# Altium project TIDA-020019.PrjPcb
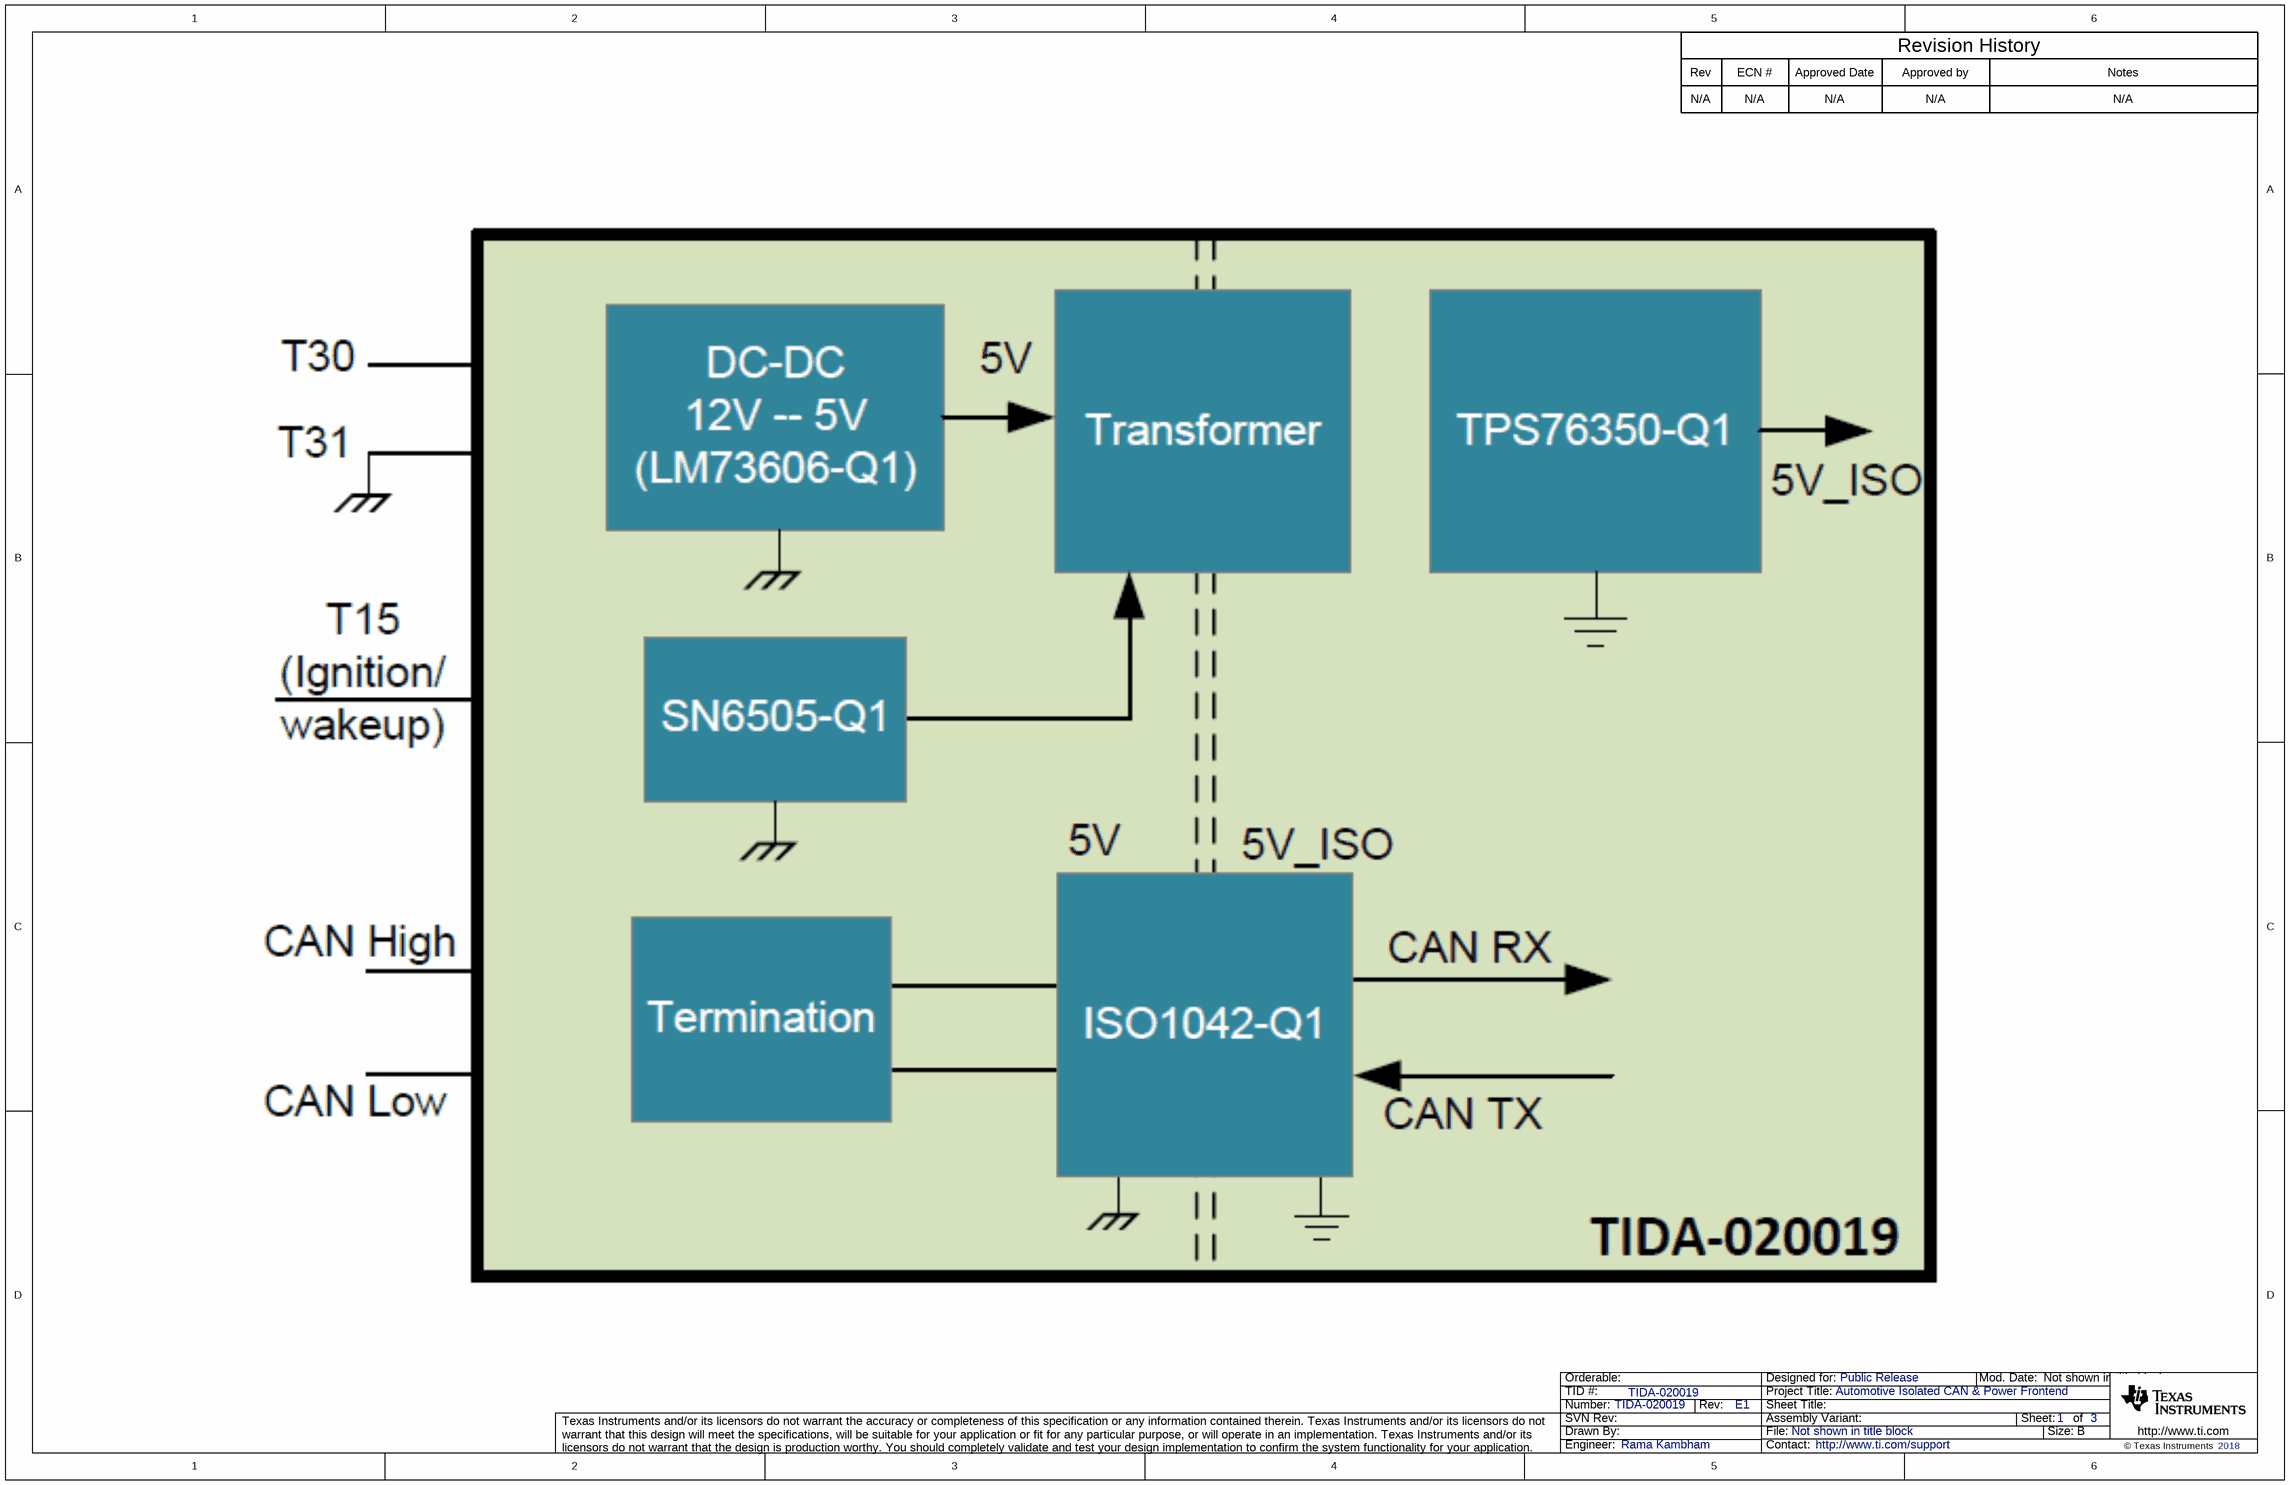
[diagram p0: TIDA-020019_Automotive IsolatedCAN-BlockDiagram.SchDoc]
CopyrightYear: 2018; PCB_Layout: Rama Kambham; PCB_Rev: E1; PRJ_Customer: Public Release; PRJ_Engineer: Rama Kambham; PRJ_Number: TIDA-020019; PRJ_Title: Automotive Isolated CAN & Power Frontend; SCH_Rev: E1; TechSupport: http://www.ti.com/support; TID: TIDA-020019
3 sheets, 62 parts. Net scope: global (net labels, ports and power ports of the same name join across sheets).
Board file: TIDA-020019_AutomotiveIsolatedCAN-Layout.PcbDoc
Sheets:
  TIDA-020019_Automotive IsolatedCAN-BlockDiagram.SchDoc
  TIDA-020019_Automotive IsolatedCAN-SCH-Page1.SchDoc
  TIDA-020019_Automotive IsolatedCAN-SCH-HW.SchDoc

## Sheet TIDA-020019_Automotive IsolatedCAN-BlockDiagram.SchDoc
size 431 x 279 mm; Date: Not shown in title block; ApprovedBy: Not shown in title block; CheckedBy: Not shown in title block; Author: Not shown in title block; CompanyName: Not shown in title block; Engineer: Not shown in title block; Organization: Not shown in title block; Address1: Not shown in title block; Address2: Not shown in title block; Address3: Not shown in title block; Address4: Not shown in title block; DocumentNumber: 1; Revision: Use project parameter SCH_Rev; SheetNumber: 1; SheetTotal: 3; PageSetup: Record=PageOptions¦CenterHorizontal=True¦CenterVertical=True¦PrintScale=1.00¦XCorrection=1.00¦YCorrection=1.00¦PrintKind=0¦BorderSize=5000000¦LeftOffset=0¦BottomOffset=0¦Orientation=2¦PaperLength=1000¦PaperWidth=1000¦Scale=100¦PaperSource=15¦PrintQuality=600¦MediaType=1¦DitherType=10¦PaperKind=Letter¦PrintScaleMode=1

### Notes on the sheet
- Rev
- N/A
- ECN #
- Approved Date
- Approved by
- Revision History
- Notes

## Sheet TIDA-020019_Automotive IsolatedCAN-SCH-Page1.SchDoc
size 431 x 279 mm; Date: Not shown in title block; ApprovedBy: Not shown in title block; CheckedBy: Not shown in title block; Author: Not shown in title block; CompanyName: Not shown in title block; DrawnBy: Rama Kambham; Engineer: Not shown in title block; Organization: Not shown in title block; Address1: Not shown in title block; Address2: Not shown in title block; Address3: Not shown in title block; Address4: Not shown in title block; DocumentNumber: 2; Revision: Use project parameter SCH_Rev; SheetNumber: 2; SheetTotal: 3; PageSetup: Record=PageOptions¦CenterHorizontal=True¦CenterVertical=True¦PrintScale=1.00¦XCorrection=1.00¦YCorrection=1.00¦PrintKind=0¦BorderSize=5000000¦LeftOffset=0¦BottomOffset=0¦Orientation=2¦PaperLength=1000¦PaperWidth=1000¦Scale=100¦PaperSource=15¦PrintQuality=600¦MediaType=1¦DitherType=10¦PaperKind=Letter¦PrintScaleMode=1
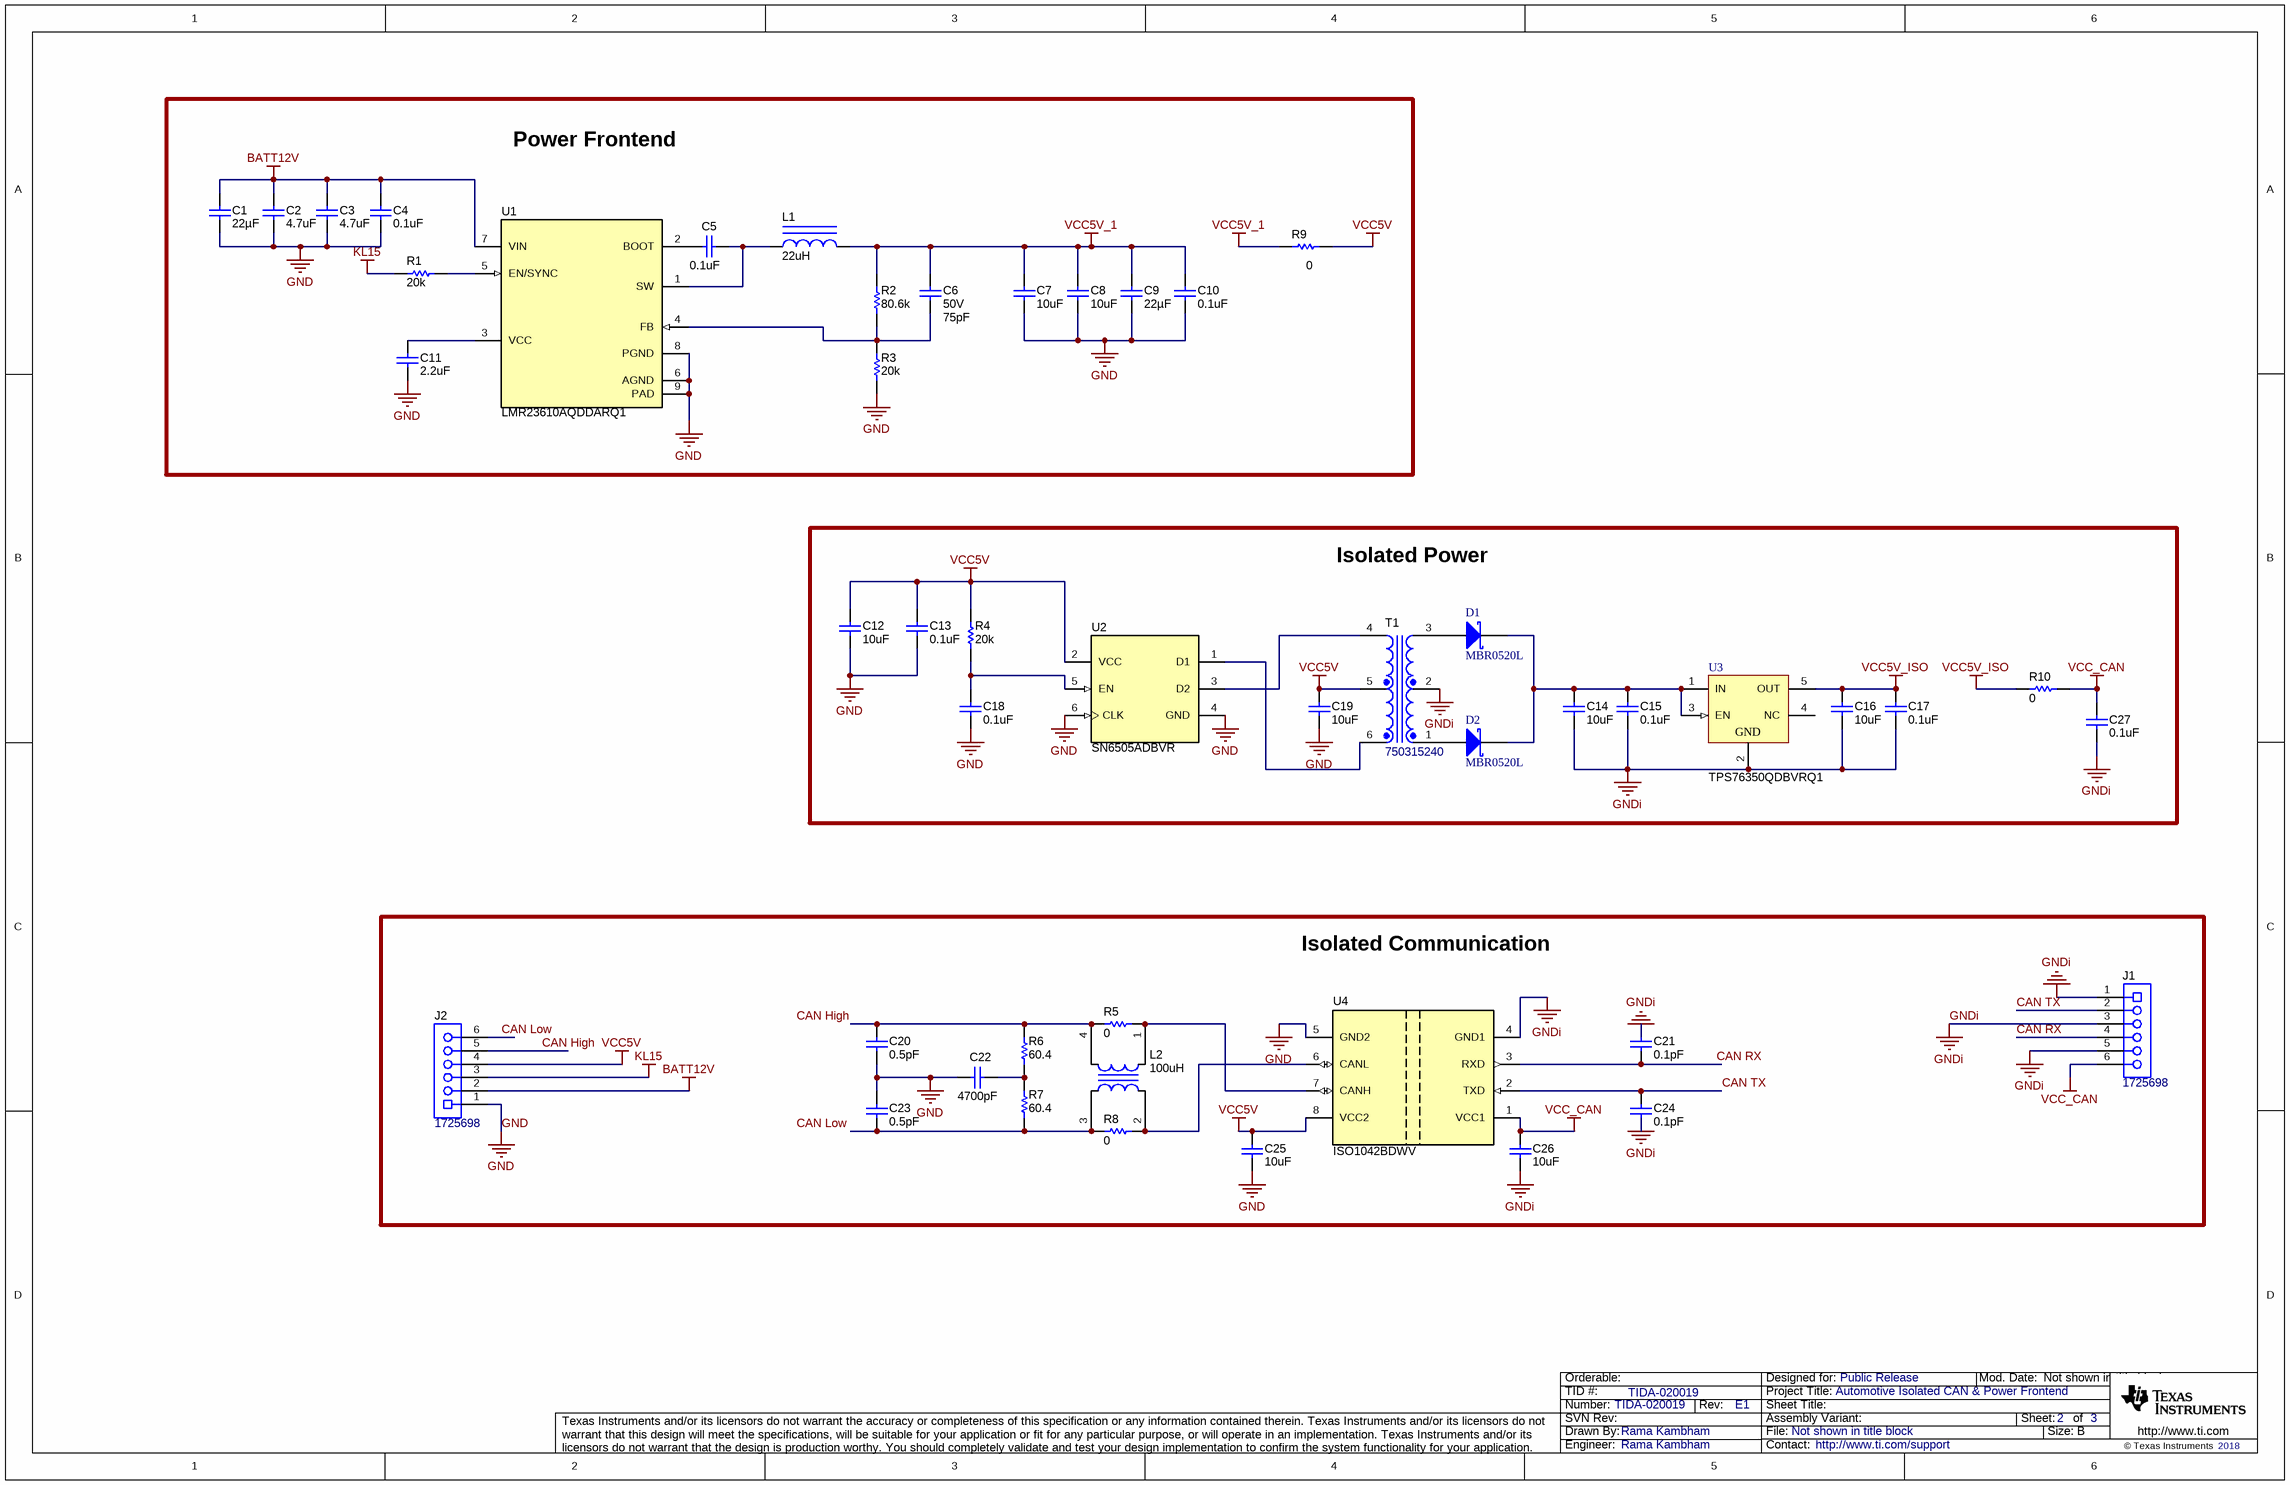
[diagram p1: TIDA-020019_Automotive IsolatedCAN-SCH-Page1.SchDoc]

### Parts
C1  ValueDisplayed: 22µF  [0805L]  (hidden comment: GRT21BR61E226ME13L)
C2  ValueDisplayed: 4.7uF  [0805L]  (hidden comment: GRT21BR61H475KE13L)
C3  ValueDisplayed: 4.7uF  [0805L]  (hidden comment: GRT21BR61H475KE13L)
C4  ValueDisplayed: 0.1uF  [0603S]  (hidden comment: CGA3E2X7R1H104K080AA)
C5  ValueDisplayed: 0.1uF  [0603S]  (hidden comment: GCM188R71C104KA37J)
C6  VDC_V: 50V  ValueDisplayed: 75pF  [0402S]  (hidden comment: GRM1555C1H750JA01D)
C7  ValueDisplayed: 10uF  [0603S]  (hidden comment: GRT188C81A106ME13D)
C8  ValueDisplayed: 10uF  [0603S]  (hidden comment: GRT188C81A106ME13D)
C9  ValueDisplayed: 22µF  [0805L]  (hidden comment: GRT21BR61E226ME13L)
C10  ValueDisplayed: 0.1uF  [0402S]  (hidden comment: GCM155R71A104KA55D)
C11  ValueDisplayed: 2.2uF  [0603S]  (hidden comment: GRT188R61H225KE13D)
C12  ValueDisplayed: 10uF  [0603S]  (hidden comment: GRT188C81A106ME13D)
C13  ValueDisplayed: 0.1uF  [0402S]  (hidden comment: GCM155R71A104KA55D)
C14  ValueDisplayed: 10uF  [0603S]  (hidden comment: GRT188C81A106ME13D)
C15  ValueDisplayed: 0.1uF  [0402S]  (hidden comment: GCM155R71A104KA55D)
C16  ValueDisplayed: 10uF  [0603S]  (hidden comment: GRT188C81A106ME13D)
C17  ValueDisplayed: 0.1uF  [0402S]  (hidden comment: GCM155R71A104KA55D)
C18  ValueDisplayed: 0.1uF  [0402S]  (hidden comment: GCM155R71A104KA55D)
C19  ValueDisplayed: 10uF  [0603S]  (hidden comment: GRT188C81A106ME13D)
C20  ValueDisplayed: 0.5pF  [0805L]  (hidden comment: GQM2195C2AR50CB01D)
C21  ValueDisplayed: 0.1pF  [0402S]  (hidden comment: GRM1555C1HR10WA01D)
C22  ValueDisplayed: 4700pF  [0603S]  (hidden comment: CGA3E2X7R2A472K080AA)
C23  ValueDisplayed: 0.5pF  [0805L]  (hidden comment: GQM2195C2AR50CB01D)
C24  ValueDisplayed: 0.1pF  [0402S]  (hidden comment: GRM1555C1HR10WA01D)
C25  ValueDisplayed: 10uF  [0603S]  (hidden comment: GRT188C81A106ME13D)
C26  ValueDisplayed: 10uF  [0603S]  (hidden comment: GRT188C81A106ME13D)
C27  ValueDisplayed: 0.1uF  [0402S]  (hidden comment: GCM155R71A104KA55D)
D1  MBR0520L  [ONSC-SOD-123-2-425-04_V]
D2  MBR0520L  [ONSC-SOD-123-2-425-04_V]
J1  1725698  [Phoenix_1725698]
J2  1725698  [Phoenix_1725698]
L1  ValueDisplayed: 22uH  [WE-PD_7345_PlasticBase]  (hidden comment: 7447779122)
L2  ValueDisplayed: 100uH  [ACT45B_NoSilk]  (hidden comment: ACT45B-101-2P-TL003)
R1  ValueDisplayed: 20k  [0402S]  (hidden comment: ERJ-2GEJ203X)
R2  ValueDisplayed: 80.6k  [0402S]  (hidden comment: CRCW040280K6FKED)
R3  ValueDisplayed: 20k  [0402S]  (hidden comment: ERJ-2GEJ203X)
R4  ValueDisplayed: 20k  [0402S]  (hidden comment: ERJ-2GEJ203X)
R5  ValueDisplayed: 0  [0402S]  (hidden comment: CRCW04020000Z0ED)
R6  ValueDisplayed: 60.4  [1206L]  (hidden comment: ERJ-8ENF60R4V)
R7  ValueDisplayed: 60.4  [1206L]  (hidden comment: ERJ-8ENF60R4V)
R8  ValueDisplayed: 0  [0402S]  (hidden comment: CRCW04020000Z0ED)
R9  ValueDisplayed: 0  [0402S]  (hidden comment: CRCW04020000Z0ED)
R10  ValueDisplayed: 0  [0402S]  (hidden comment: CRCW04020000Z0ED)
T1  750315240  [Wurth_750315240]
U1  LMR23610AQDDARQ1  [DDA0008E_L]
U2  SN6505ADBVR  [DBV0006A_L]
U3  TPS76350QDBVRQ1  [DBV0005A_N]
U4  ISO1042BDWV  [DWV0008A]

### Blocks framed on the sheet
Power Frontend: C1-C11 L1 R1-R3 R9 U1
Isolated Power: C12-C19 C27 D1 D2 R4 R10 T1 U2 U3
Isolated Communication: C20-C26 J1 J2 L2 R5-R8 U4

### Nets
BATT12V: C1.1 C2.1 C3.1 C4.1 J2.2 U1.7(VIN)
GND: C1.2 C2.2 C3.2 C4.2 C7.2 C8.2 C9.2 C10.2 C11.2 C12.2 C13.2 C18.2 C19.2 C20.2 C22.2 C23.1 C25.2 J2.1 R3.1 U1.6(AGND) U1.8(PGND) U1.9(PAD) U2.4(GND) U2.6(CLK) U4.5(GND2)
GNDi: C14.2 C15.2 C16.2 C17.2 C21.1 C24.2 C26.2 C27.2 J1.1 J1.3 J1.5 T1.2 U3.2(GND) U4.4(GND1)
KL15: J2.3 R1.2
VCC5V: C12.1 C13.1 C19.1 C25.1 J2.4 R4.2 R9.2 T1.5 U2.2(VCC) U4.8(VCC2)
VCC5V_1: C6.1 C7.1 C8.1 C9.1 C10.1 L1.2 R2.2 R9.1
VCC5V_ISO: C16.1 C17.1 R10.1 U3.5(OUT)
VCC_CAN: C26.1 C27.1 J1.6 R10.2 U4.1(VCC1)
CAN High: J2.5
CAN Low: J2.6
CAN RX: C21.2 J1.4 U4.3(RXD)
CAN TX: C24.1 J1.2 U4.2(TXD)
NetC5_1: C5.1 L1.1 U1.1(SW)
NetC5_2: C5.2 U1.2(BOOT)
NetC6_2: C6.2 R2.1 R3.2 U1.4(FB)
NetC11_1: C11.1 U1.3(VCC)
NetC14_1: C14.1 C15.1 D1.1(K) D2.1(K) U3.1(IN) U3.3(EN)
NetC18_1: C18.1 R4.1 U2.5(EN)
NetC20_1: C20.1 L2.4 R5.1 R6.2
NetC22_1: C22.1 R6.1 R7.2
NetC23_2: C23.2 L2.3 R7.1 R8.1
NetD1_2: D1.2(A) T1.3
NetD2_2: D2.2(A) T1.1
NetL2_1: L2.1 R5.2 U4.7(CANH)
NetL2_2: L2.2 R8.2 U4.6(CANL)
NetR1_1: R1.1 U1.5(EN/SYNC)
NetT1_4: T1.4 U2.3(D2)
NetT1_6: T1.6 U2.1(D1)

Not connected (* = marked no-connect by the designer): U3 4(NC)

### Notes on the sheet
- Labels drawn without touching a wire or pin: CAN High, CAN Low

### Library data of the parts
C1 C9 = CMP-0084680-1: CAP, CERM, 22 µF, 25 V,+/- 20%, X5R, AEC-Q200 Grade 3, 0805; Manufacturer: MuRata; SizeX_mm: 2; SizeAreaWB_mm2: 6.75; Cap_Case: 0805; AEC Grade: 3; SizeY_mm: 1.25; SizeArea_mm2: 2.5; SizeZ_mm: 1.45; U/M: EA; Polarized: N; VDC_V: 25V; AEC Category: Q200; Value: 22uF; TaMin_C: -55°C; AEC Qualified: Y; TaMax_C: 85°C
C2 C3 = CMP-0008380-1: CAP, CERM, 4.7 uF, 50 V, +/- 10%, X5R, AEC-Q200 Grade 3, 0805; Manufacturer: MuRata; TaMin_C: -55°C; Polarized: N; SizeAreaWB_mm2: 6.75; Value1: Unknown; U/M: EA; Value: 4.7uF; TaMax_C: 85°C; SizeZ_mm: 1.45; SizeX_mm: 2; SizeY_mm: 1.25; Cap_Case: 0805; Value2: 50V; SizeArea_mm2: 2.5; AEC Qualified: Y; Cap_F: 4.7µF; AEC Grade: 3; AEC Category: Q200
C4 = CMP-0007078-1: CAP, CERM, 0.1 uF, 50 V, +/- 10%, X7R, AEC-Q200 Grade 1, 0603; Manufacturer: TDK; TaMin_C: -55°C; ESR_ohm: 0.0296; Polarized: N; SizeAreaWB_mm2: 4.68; Value1: 0.0296 ohm; U/M: EA; Value: 0.1uF; TaMax_C: 125°C; SizeZ_mm: 1; SizeX_mm: 1.6; SizeY_mm: 0.8; Cap_Case: 0603; Value2: 50V; SizeArea_mm2: 1.28; AEC Qualified: Y; Cap_F: 100nF; IRMS_A: 971.99mA; AEC Category: Q200
C5 = CMP-0007135-4: CAP, CERM, 0.1 uF, 16 V, +/- 10%, X7R, AEC-Q200 Grade 1, 0603; Manufacturer: MuRata; TaMin_C: -55°C; Polarized: N; SizeAreaWB_mm2: 4.68; Value1: Unknown; U/M: EA; Value: 0.1uF; TaMax_C: 125°C; SizeZ_mm: 1; SizeX_mm: 1.6; SizeY_mm: 0.8; Cap_Case: 0603; Value2: 16V; SizeArea_mm2: 1.28; AEC Qualified: Y; Cap_F: 100nF; AEC Category: Q200
C6 = CMP-0006489-1: CAP, CERM, 75 pF, 50 V, +/- 5%, C0G/NP0, 0402; Manufacturer: MuRata; TaMin_C: -55°C; Polarized: N; SizeAreaWB_mm2: 3; Value1: Unknown; U/M: EA; Value: 75pF; TaMax_C: 125°C; SizeZ_mm: 0.6; SizeX_mm: 1; SizeY_mm: 0.5; Cap_Case: 0402; AEC Category: Q200
C7 C8 C12 C14 C16 C19 C25 C26 = CMP-0007500-1: CAP, CERM, 10 uF, 10 V, +/- 20%, X6S, AEC-Q200 Grade 2, 0603; Manufacturer: MuRata; TaMin_C: -55°C; Polarized: N; SizeAreaWB_mm2: 4.68; Value1: Unknown; U/M: EA; Value: 10uF; TaMax_C: 105°C; SizeZ_mm: 1; SizeX_mm: 1.6; SizeY_mm: 0.8; Cap_Case: 0603; Value2: 10V; SizeArea_mm2: 1.28; AEC Qualified: Y; Cap_F: 10µF; AEC Grade: 2; AEC Category: Q200
C10 C13 C15 C17 C18 C27 = CMP-0006350-1: CAP, CERM, 0.1 uF, 10 V, +/- 10%, X7R, AEC-Q200 Grade 1, 0402; Manufacturer: MuRata; TaMin_C: -55°C; Polarized: N; SizeAreaWB_mm2: 3; Value1: Unknown; U/M: EA; Value: 0.1uF; TaMax_C: 125°C; SizeZ_mm: 0.6; SizeX_mm: 1; SizeY_mm: 0.5; Cap_Case: 0402; Value2: 10V; AEC Qualified: Y; Cap_F: 100nF; AEC Category: Q200
C11 = CMP-0007502-1: CAP, CERM, 2.2 uF, 50 V, +/- 10%, X5R, AEC-Q200 Grade 3, 0603; Manufacturer: MuRata; TaMin_C: -55°C; Polarized: N; SizeAreaWB_mm2: 4.68; Value1: Unknown; U/M: EA; Value: 2.2uF; TaMax_C: 85°C; SizeZ_mm: 1; SizeX_mm: 1.6; SizeY_mm: 0.8; Cap_Case: 0603; Value2: 50V; SizeArea_mm2: 1.28; AEC Qualified: Y; Cap_F: 2.2µF; AEC Grade: 3; AEC Category: Q200
C20 C23 = CMP-0008057-1: CAP, CERM, 0.5 pF, 100 V, +/- 5%, C0G/NP0, 0805; Manufacturer: MuRata; TaMin_C: -55°C; Polarized: N; SizeAreaWB_mm2: 6.75; Value1: Unknown; U/M: EA; Value: 0.5pF; TaMax_C: 125°C; SizeZ_mm: 1.45; SizeX_mm: 2; SizeY_mm: 1.25; Cap_Case: 0805; Value2: 100V; SizeArea_mm2: 2.5; AEC Category: Q200
C21 C24 = CMP-0006499-2: CAP, CERM, 0.1pF, 50 V, +/- 50%, C0G/NP0, 0402; Manufacturer: MuRata; TaMin_C: -55°C; Polarized: N; SizeAreaWB_mm2: 3; Value1: Unknown; U/M: EA; TaMax_C: 125°C; SizeZ_mm: 0.6; SizeX_mm: 1; SizeY_mm: 0.5; Cap_Case: 0402; Value2: 50V; AEC Category: Q200
C22 = CMP-0007088-4: CAP, CERM, 4700 pF, 100 V, +/- 10%, X7R, AEC-Q200 Grade 1, 0603; Manufacturer: TDK; TaMin_C: -55°C; ESR_ohm: 0.469862; Polarized: N; SizeAreaWB_mm2: 4.68; Value1: 0.469862 ohm; U/M: EA; Value: 4700pF; TaMax_C: 125°C; SizeZ_mm: 1; SizeX_mm: 1.6; SizeY_mm: 0.8; Cap_Case: 0603; Value2: 100V; SizeArea_mm2: 1.28; AEC Qualified: Y; Cap_F: 4.7nF; IRMS_A: 323.35mA; AEC Category: Q200
D1 D2 = CMP-2000-04926-1: Schottky Diode, 20V, 0.2A, 2-pin SOD-123, RoHS, Tape and Reel; Manufacturer: FairchildSemiconductor; Peak Forward Voltage: 0.385V; Rad Hard: No; Peak Non-Repetitive Surge Current: 5.5A; Peak Average Forward Current: 0.5A; Peak Reverse Current: 250uA; Configuration: Single
J1 J2 = CMP-0055512-1: Terminal Block, 6x1, 2.54mm, TH; Manufacturer: Phoenix Contact; CNHeader: FALSE; Current_A: 6A; Cert_CSA: Y; Voltage_V: 160V; Row_Count: 1; Pitch_mm: 2.54; CT: TRUE
L1 = CMP-0064637-2: Inductor, Shielded Drum Core, Ferrite, 22 uH, 1.41 A, 0.09 ohm, SMD; Manufacturer: Wurth Elektronik; Isat: 1.7A @ 10% inductance drop; Irms: 1.41A @ 40C rise; Green_Lifecycle: Active; SizeAreaWB_mm2: 86.49; DCR_ohm: 0.09; Green_REACh: Passed; Value: 22uH; Imax_A: 1.41A; SizeZ_mm: 4.5; SizeX_mm: 7.3; SizeArea_mm2: 53.29; Ind_H: 22µH; AEC Category: Q200
L2 = CMP-0062430-2: Inductor, Ferrite, 100 uH, 0.15 A, 2 ohm, SMD; Manufacturer: TDK; Isat: 0.15A @ % inductance drop; Green_Lifecycle: Active; SizeAreaWB_mm2: 23.1; DCR_ohm: 2; Green_REACh: Passed; Value1: 2 ohm; Value: 100uH; Imax_A: 150mA; SizeZ_mm: 3; SizeX_mm: 4.5; SizeY_mm: 3.2; Value2: 0.15A; SizeArea_mm2: 14.4; Ind_H: 100µH; AEC Category: Q200
R1 R3 R4 = CMP-0026996-1: RES, 20 k, 5%, 0.1 W, AEC-Q200 Grade 0, 0402; Manufacturer: Panasonic; Power_W: 100mW; TempCo: 200 ppm/C; Value_Code: 20k0; U/M: EA; Value: 20k; EIA_Code: E24; SizeX_mm: 1; SizeY_mm: 0.5; SizeZ_mm: 0.6; Value2: 0.1W; AEC Qualified: Y; VDC_V: 50V; AEC Grade: 0; AEC Category: Q200
R2 = CMP-0026570-1: RES, 80.6 k, 1%, 0.063 W, 0402; Manufacturer: Vishay-Dale; Power_W: 63mW; TempCo: 100 ppm/C; Value_Code: 80k6; U/M: EA; Value: 80.6k; EIA_Code: E96; SizeX_mm: 1; SizeY_mm: 0.5; SizeZ_mm: 0.6; Value2: 0.063W; VDC_V: 50V; AEC Category: Q200
R5 R8-R10 = CMP-0026822-3: RES, 0, 5%, 0.063 W, AEC-Q200 Grade 0, 0402; Manufacturer: Vishay-Dale; Power_W: 63mW; TempCo: 200 ppm/C; Value_Code: 0000; Value: 0; EIA_Code: E24; SizeX_mm: 1; SizeY_mm: 0.5; SizeZ_mm: 0.6; Value2: 0.063W; AEC Qualified: Y; VDC_V: 50V; AEC Category: Q200
R6 R7 = CMP-0017672-3: RES, 60.4, 1%, 0.25 W, AEC-Q200 Grade 0, 1206; Manufacturer: Panasonic; Power_W: 250mW; TempCo: 100 ppm/C; Value_Code: 60R4; Value: 60.4; EIA_Code: E96; SizeX_mm: 3.2; SizeY_mm: 1.6; SizeZ_mm: 1.35; Value2: 0.25W; SizeArea_mm2: 5.12; AEC Qualified: Y; VDC_V: 200V; AEC Category: Q200; AEC Grade: 0; SizeAreaWB_mm2: 10.92
T1 = CMP-0030614-1: Transformer, 110 uH, SMT; Manufacturer: Wurth Elektronik; Green_Lifecycle: Active; DCR_ohm: 0.15; Green_REACh: Passed; Value: 110uH; Lp: 110; Ind_H: 110µH
U1 = CMP-0013265-3: SIMPLE SWITCHER, 36V, 1A Synchronous Step-Down Converter, DDA0008E (SOIC-8); Alternate PartNumber: LMR23610AQDDAQ1; Manufacturer: Texas Instruments; SizeZ_mm: 1.7; SizeX_mm: 5; SizeY_mm: 6.2; SizeArea_mm2: 31; CompType: IC; U/M: EA; SizeAreaWB_mm2: 57.4
U2 = CMP-0076094-1: Low-Noise 1-A Transformer Driver for Isolated Power Supplies, Internal Clock-160kHz, DBV0006A (SOT-23-6); Manufacturer: Texas Instruments; Alternate PartNumber: SN6505ADBVT; SizeAreaWB_mm2: 14.82; SizeArea_mm2: 8.12; SizeZ_mm: 1.45; Green_REACh: Passed; SizeY_mm: 2.9; Green_Lifecycle: Active; U/M: EA; CompType: IC; SizeX_mm: 2.8
U3 = CMP-0035574-1: Single Output Automotive LDO, 150 mA, Fixed 5 V Output, 2.7 to 10 V Input, 5-pin SOT-23 (DBV), -40 to 125 degC, Green (RoHS & no Sb/Br); Manufacturer: Texas Instruments; Vout Adj(Min)(V): 5; Vin(Min)(V): 2.7; Vin(Max)(V): 10; SubFamily: Single Channel LDO; Vdo(Typ)(mV): 300; Fixed Output Options(V): 5.0; Accuracy(%): 3; Iq(Typ)(mA): 0.08; Iout(Max)(A): 0.15
U4 = CMP-0077951-1: Reinforced Isolated CAN XCVRs with 70V Protection Voltage and CAN FD, DWV0008A (SOIC-8); Alternate PartNumber: ISO1042BDWVR; Alternate Manufacturer: Texas Instruments; SizeAreaWB_mm2: 105.975; SizeZ_mm: 2.8; SizeX_mm: 11.5; SizeY_mm: 5.85; SizeArea_mm2: 67.275; CompType: IC; AEC Qualified: N; AEC Category: Q200

## Sheet TIDA-020019_Automotive IsolatedCAN-SCH-HW.SchDoc
size 431 x 279 mm; Date: Not shown in title block; ApprovedBy: Not shown in title block; CheckedBy: Not shown in title block; Author: Not shown in title block; CompanyName: Not shown in title block; Engineer: Not shown in title block; Organization: Not shown in title block; Address1: Not shown in title block; Address2: Not shown in title block; Address3: Not shown in title block; Address4: Not shown in title block; DocumentNumber: 3; Revision: Use project parameter SCH_Rev; SheetNumber: 3; SheetTotal: 3; PageSetup: Record=PageOptions¦CenterHorizontal=True¦CenterVertical=True¦PrintScale=1.00¦XCorrection=1.00¦YCorrection=1.00¦PrintKind=0¦BorderSize=5000000¦LeftOffset=0¦BottomOffset=0¦Orientation=2¦PaperLength=1000¦PaperWidth=1000¦Scale=100¦PaperSource=15¦PrintQuality=600¦MediaType=1¦DitherType=10¦PaperKind=Letter¦PrintScaleMode=1
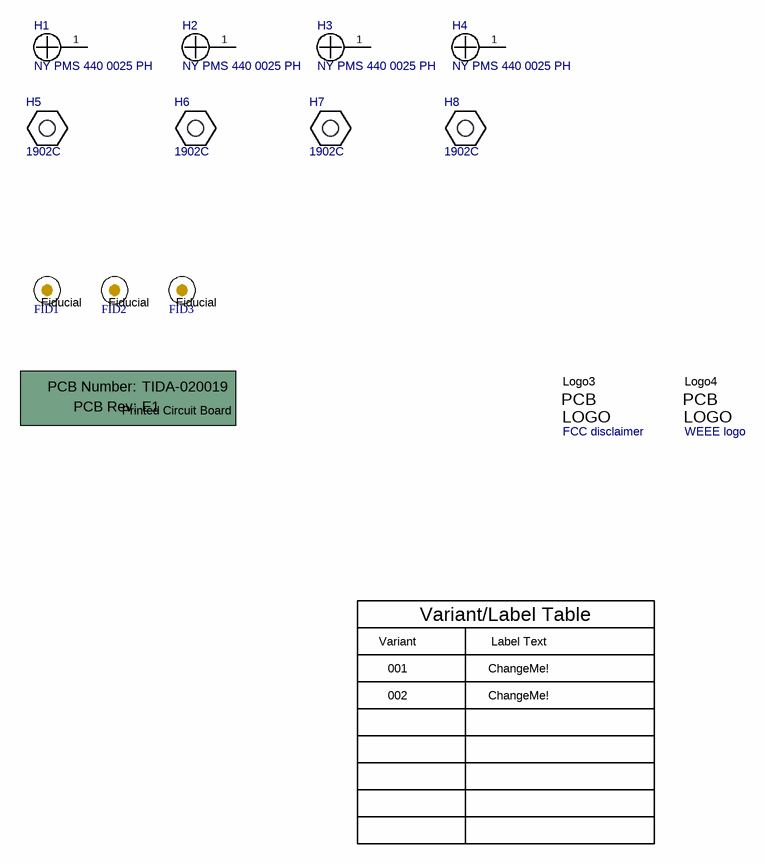
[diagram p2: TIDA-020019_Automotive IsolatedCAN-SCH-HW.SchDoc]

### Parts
!PCB1  Printed Circuit Board  (mechanical)
FID1  Fiducial  [Fiducial6.4-20]
FID2  Fiducial  [Fiducial6.4-20]
FID3  Fiducial  [Fiducial6.4-20]
H1  NY PMS 440 0025 PH  [NY PMS 440 0025 PH]
H2  NY PMS 440 0025 PH  [NY PMS 440 0025 PH]
H3  NY PMS 440 0025 PH  [NY PMS 440 0025 PH]
H4  NY PMS 440 0025 PH  [NY PMS 440 0025 PH]
H5  1902C  [Keystone_1902C]
H6  1902C  [Keystone_1902C]
H7  1902C  [Keystone_1902C]
H8  1902C  [Keystone_1902C]
Logo3  FCC disclaimer  [FCC_disclaimer]  (no BOM)
Logo4  WEEE logo  [WEEE_Minimum]  (no BOM)

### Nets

Not connected (* = marked no-connect by the designer): H1 1; H2 1; H3 1; H4 1

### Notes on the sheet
- Variant
- Variant/Label Table
- Label Text
- 001
- 002
- ChangeMe!

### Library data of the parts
!PCB1 = CMP-0003618-2: Manufacturer: Any; PartNumber: TIDA-020019
FID1-FID3 = CMP-0077181-1: Fiducial mark.  There is nothing to buy or mount.
H1-H4 = CMP-0003617-1: Machine Screw, Round, #4-40 x 1/4, Nylon, Philips panhead; Manufacturer: B&F Fastener Supply; CompType: Hardware
H5-H8 = CMP-0003610-1: Standoff, Hex, 0.5"L #4-40 Nylon; Manufacturer: Keystone; CompType: Hardware
Logo3 = CMP-0074847-1: FCC_disclaimer
Logo4 = CMP-0074769-1

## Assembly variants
001: not fitted FID1 FID2 FID3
